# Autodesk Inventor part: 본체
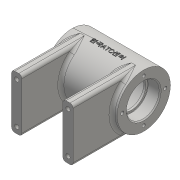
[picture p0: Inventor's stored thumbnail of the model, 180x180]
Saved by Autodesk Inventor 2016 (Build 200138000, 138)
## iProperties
Created: 2020-07
Part Number: 본체
Material: Generic
Document SubType Name: Modeling
Designer: user
Density: 1 g/cm^3
Appearance: Default
Author: user
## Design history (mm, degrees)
sketch "스케치1"
  geometry: L1 (-35, 0)-(35, 0); L2 (-35, 0)-(-35, 26); L3 (-35, 26)-(35, 26); L4 (35, 26)-(35, 0); L5 (-35, 16)-(-23, 16); L6 (-23, 16)-(-23, 14); L7 (-23, 14)-(-21, 14); L8 (-21, 14)-(-21, 21); L9 (-21, 21)-(21, 21); L10 (21, 21)-(21, 14); L11 (21, 14)-(23, 14); L12 (23, 14)-(23, 16); L13 (23, 16)-(35, 16); 2 further points
  constraints: 26 end point, 9 perpendicular, 3 horizontal, 2 horizontal alignment, 2 point on line, 1 coincident, 1 midpoint, 1 vertical
  dimensions: "d0" = 28 diameter of L11 L1; "d1" = 32 diameter of L13 L1; "d2" = 52 diameter of L3 L1; "d3" = 42 diameter of L9 L1; "d4" = 12 distance of L5.start L5.end; "d5" = 2 distance of L6.end L7.end; "d6" = 42 distance of L8.end L9.end; "d7" = 12 distance of L12.end L13.end; "d8" = 2 distance of L10.end L11.end
revolve "회전1" sketch "스케치1" stored, may be unused: angle "d9" = 90 deg
node "작업 평면1"
sketch "스케치2"
  geometry: L1 (0, -26)-(-64, -26); L2 (-64, -26)-(-64, 26); L3 (-64, 26)-(0, 26); A1 r 26 centre (0, 0) between (0, -26) and (0, 26) reference; A2 r 26 centre (0, 0) between (0, -26) and (0, 26) reference; 1 further point
  constraints: 6 end point, 4 point on circle, 2 tangent, 1 horizontal, 1 parallel, 1 perpendicular
  dimensions: "d11" = 64 distance from line of L2 point (0, 0)
extrude "돌출1" join sketch "스케치2" distance "d12" = 10; taper "d13" = 0 deg
node "작업 평면2"
sketch "스케치3"
  geometry: C1 r 5 at (0, 0); 1 further point
  constraints: 1 centre point, 1 coincident
  dimensions: "d15" = 10 diameter of C1
extrude "돌출2" join sketch "스케치3" stored distance "d16" = 10; taper "d17" = 0 deg
hole "구멍1" diameter "d20" = 5.188; stored, may be unused: countersink angle "d24" = 90 deg, drill point angle "d26" = 118 deg; dims "d18" = 10, "d19" = 10, "d21" = 12, "d22" = 4, "d23" = 2, "d25" = 16
sketch "스케치4"
  geometry: L1 (0, 0)-(0, 21)
  constraints: 2 end point, 1 vertical
  dimensions: "d27" = 21 distance of L1.start L1.end
hole "구멍2" sketch "스케치4" at (0, 21) diameter "d28" = 3.242; stored, may be unused: countersink angle "d32" = 90 deg, drill point angle "d34" = 118 deg; dims "d29" = 8, "d30" = 4, "d31" = 2, "d33" = 10
sketch "스케치5"
  geometry: L1 (-5, 6)-(45, 6); L2 (45, 6)-(45, 46); L3 (45, 46)-(-5, 46); L4 (-5, 46)-(-5, 6); L5 (-5, 6)-(45, 46); L6 (45, 6)-(-5, 46); L7 (-10, 0)-(-10, 52) reference; 1 further point
  constraints: 12 end point, 2 midpoint, 2 parallel, 1 horizontal, 1 perpendicular
  dimensions: "d39" = 40 distance of L1.end L2.end; "d40" = 5 distance between parallel lines of L7 L4
hole "구멍3" sketch "스케치5" at (-5, 46), (45, 46), (45, 6), (-5, 6) diameter "d41" = 4.134; stored, may be unused: countersink angle "d45" = 90 deg, drill point angle "d47" = 118 deg; dims "d42" = 10, "d43" = 4, "d44" = 2, "d46" = 10
sketch "스케치6"
  geometry: L1 (29, -5)-(25.515, -5) reference; L2 (25.515, 5)-(29, 5) reference; L3 (29, 5)-(29, 2.594) reference; L4 (29, 2.594)-(20.839, 2.594) reference; L5 (20.839, -2.594)-(29, -2.594) reference; L6 (29, -2.594)-(29, -5) reference; L7 (0, 0)-(-27.251, -9.919); L8 (-27.251, -9.919)-(-25.199, -15.557); L9 (-25.199, -15.557)-(-21.72, -14.291); L10 (0, 0)-(-26, 0); A1 r 26 centre (0, 0) between (25.515, 5) and (25.515, -5) reference; A2 r 21 centre (0, 0) between (20.839, 2.594) and (20.839, -2.594) reference; A3 r 26 centre (0, 0) between (0, 26) and (0, -26) reference; A4 r 26 centre (0, 0) between (-24.432, -8.893) and (-21.72, -14.291); 1 further point
  constraints: 8 end point, 6 point on circle, 1 centre point, 1 parallel, 1 perpendicular, 1 point on line
  dimensions: "d48" = 20 deg angle of L7 L10; "d49" = 29 distance from line of point (0, 0) L8; "d50" = 12 diameter of L9 L7
revolve "회전2" sketch "스케치6" stored, may be unused: angle "d51" = 90 deg
hole "구멍4" diameter "d54" = 5.188; stored, may be unused: countersink angle "d58" = 90 deg, drill point angle "d60" = 118 deg; dims "d52" = 10, "d53" = 10, "d55" = 12, "d56" = 4, "d57" = 2, "d59" = 16
fillet "모깎기1" dims "d61" = 2
fillet "모깎기2" dims "d62" = 3
fillet "모깎기3" dims "d63" = 3
fillet "모깎기4" dims "d64" = 3, "d65" = 0.3
chamfer "모따기1" distance "d66" = 1; stored, may be unused: second distance "d67" = 2, angle "d68" = 45 deg
sketch "스케치8"
  geometry: L1 (-35, -26)-(-35, 26) reference; L2 (-35, 26)-(35, 26) reference; 2 further points
  constraints: 1 other
  dimensions: "d74" = 35 distance from line of L1 point (0, 0); "d75" = 26 distance from line of L2 point (0, 0)
feature "엠보싱2" sketch "스케치8" dims "d0" = 28, "d1" = 32, "d2" = 52, "d3" = 42, "d4" = 12, "d5" = 2, "d6" = 42, "d7" = 12, "d8" = 2, "d11" = 64, "d76" = 0.5, "d77" = 0
node "솔리드1"
mirror "대칭1"
pattern_circular "원형 패턴1" dims angle "d36" = 360 deg
mirror "대칭2"
node "절단 모서리 투영1"
other parameters: "d14" = 29
